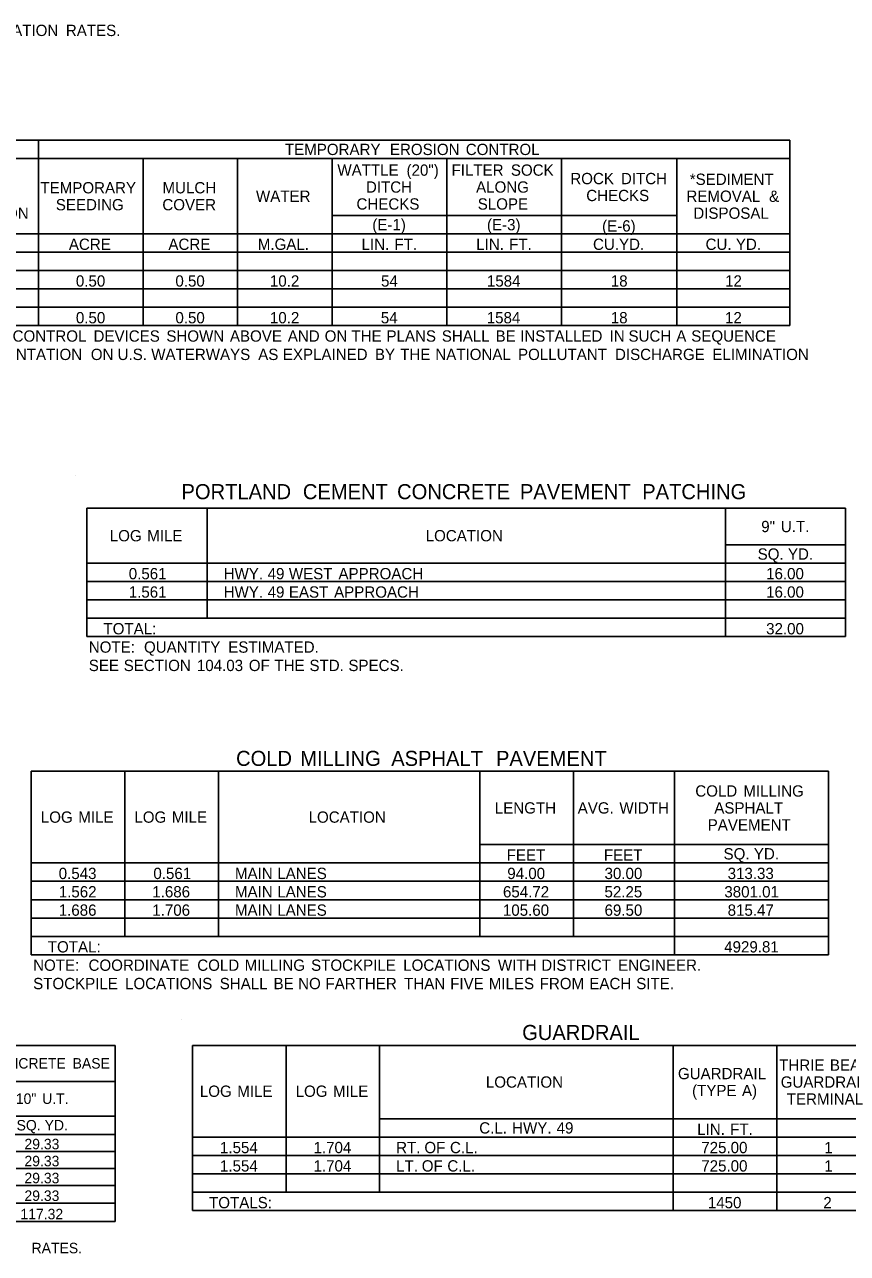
# Model space of a CAD drawing. Extents: x 107 to 7866, y 32 to 1473.
# Drawn here: x 2772 to 3209, y 41 to 694 of the extents above; entities that cross this region are included whole.
import ezdxf

# ---------------------------------------------------------------- set-up
doc = ezdxf.new("R2010")
doc.units = 0
doc.layers.add('Default', color=7, linetype='Continuous')
doc.layers.add('R_No Plot', color=7, linetype='Continuous')

msp = doc.modelspace()

# ---------------------------------------------------------------- linework, layer by layer
at = {"layer": 'Default'}
for p, q in [((2198.44, 632.71), (3178.81, 632.71)), ((2779.54, 534.24), (2779.54, 632.71)), ((2779.54, 622.96), (2779.54, 632.71)), ((3178.81, 573.24), (3178.81, 632.71)), ((2518.24, 622.96), (3178.81, 622.96)), ((2835.12, 534.24), (2835.12, 622.96)), ((2885.33, 534.24), (2885.33, 622.96)), ((2935.54, 534.24), (2935.54, 622.96)), ((2996.48, 534.24), (2996.48, 622.96)), ((3057.42, 534.24), (3057.42, 622.96)), ((3118.84, 534.24), (3118.84, 622.96)), ((2935.54, 592.74), (3118.84, 592.74)), ((2518.24, 582.99), (3178.81, 582.99)), ((2779.54, 543.99), (2779.54, 582.99)), ((2835.12, 534.24), (2835.12, 582.99)), ((2885.33, 534.24), (2885.33, 582.99)), ((2935.54, 543.99), (2935.54, 582.99)), ((2996.48, 543.99), (2996.48, 582.99)), ((3057.42, 543.99), (3057.42, 582.99)), ((3118.84, 582.99), (3178.81, 582.99)), ((3118.84, 543.99), (3118.84, 582.99)), ((2198.44, 573.24), (3178.81, 573.24)), ((3178.81, 543.99), (3178.81, 573.24)), ((2198.44, 563.49), (3178.81, 563.49)), ((2198.44, 553.74), (3178.81, 553.74)), ((2198.44, 543.99), (3178.81, 543.99)), ((2568.46, 543.99), (2779.54, 543.99)), ((2779.54, 543.99), (2835.12, 543.99)), ((2835.12, 543.99), (3178.81, 543.99)), ((3178.81, 534.24), (3178.81, 543.99)), ((2198.44, 534.24), (3178.81, 534.24)), ((2805.26, 437.25), (3208.43, 437.25)), ((2805.26, 369), (2805.26, 437.25)), ((2805.26, 369), (2805.26, 437.25)), ((2869.13, 378.75), (2869.13, 437.25)), ((3144.56, 369), (3144.56, 437.25)), ((3144.56, 417.75), (3144.56, 437.25)), ((3208.43, 369), (3208.43, 437.25)), ((3208.43, 369), (3208.43, 437.25)), ((3144.56, 417.75), (3208.43, 417.75)), ((2805.26, 408), (3208.43, 408)), ((2805.26, 408), (3208.43, 408)), ((2805.26, 398.25), (3208.43, 398.25)), ((2805.26, 388.5), (3208.43, 388.5)), ((3144.56, 378.75), (3144.56, 388.5)), ((2805.26, 378.75), (3208.43, 378.75)), ((2805.26, 378.75), (3208.43, 378.75)), ((2805.26, 369), (3208.43, 369)), ((2775.69, 297.5), (3199.33, 297.5)), ((2775.69, 200), (2775.69, 297.5)), ((2775.69, 200), (2775.69, 297.5)), ((2825.42, 209.75), (2825.42, 297.5)), ((2875.14, 209.75), (2875.14, 297.5)), ((3014.08, 209.75), (3014.08, 297.5)), ((3063.81, 209.75), (3063.81, 297.5)), ((3117.43, 200), (3117.43, 297.5)), ((3199.33, 200), (3199.33, 297.5)), ((3014.08, 258.5), (3199.33, 258.5)), ((3014.08, 209.75), (3014.08, 258.5)), ((3063.81, 248.75), (3063.81, 258.5)), ((2775.69, 248.75), (3199.33, 248.75)), ((2825.42, 209.75), (2825.42, 248.75)), ((2875.14, 209.75), (2875.14, 248.75)), ((3117.43, 209.75), (3117.43, 248.75)), ((2775.69, 239), (3199.33, 239)), ((2775.69, 229.25), (3199.33, 229.25)), ((2775.69, 219.5), (3199.33, 219.5)), ((2775.69, 209.75), (2825.42, 209.75)), ((2775.69, 209.75), (3199.33, 209.75)), ((2875.14, 209.75), (3014.08, 209.75)), ((3014.08, 209.75), (3117.43, 209.75)), ((3117.43, 209.75), (3199.33, 209.75)), ((2775.69, 200), (3199.33, 200)), ((2855.52, 165.52), (2855.52, 165.52)), ((2198.01, 151.87), (2820.2, 151.87)), ((2820.2, 58.34), (2820.2, 151.87)), ((2820.2, 58.34), (2820.2, 151.87)), ((2861.37, 151.87), (3281.6, 151.87)), ((2861.37, 64.12), (2861.37, 151.87)), ((2861.37, 64.12), (2861.37, 151.87)), ((2911.1, 73.87), (2911.1, 151.87)), ((2960.82, 73.87), (2960.82, 151.87)), ((3116.82, 64.12), (3116.82, 151.87)), ((3171.91, 64.12), (3171.91, 151.87)), ((2624.12, 132.73), (2820.2, 132.73)), ((2671.43, 114.32), (2820.2, 114.32)), ((2960.82, 112.87), (3116.82, 112.87)), ((2960.82, 112.87), (3281.6, 112.87)), ((3171.91, 64.12), (3171.91, 112.87)), ((2576.82, 104.57), (2820.2, 104.57)), ((2624.12, 104.57), (2820.2, 104.57)), ((2861.37, 103.12), (3281.6, 103.12)), ((2911.1, 73.87), (2911.1, 103.12)), ((2960.82, 73.87), (2960.82, 103.12)), ((3116.82, 64.12), (3116.82, 103.12)), ((2198.01, 95.54), (2820.2, 95.54)), ((2861.37, 93.37), (3281.6, 93.37)), ((2198.01, 86.51), (2820.2, 86.51)), ((2861.37, 83.62), (3281.6, 83.62)), ((2198.01, 77.48), (2820.2, 77.48)), ((2861.37, 73.87), (3281.6, 73.87)), ((2198.01, 68.09), (2820.2, 68.09)), ((2198.01, 68.09), (2820.2, 68.09)), ((2861.37, 64.12), (3281.6, 64.12)), ((2198.01, 58.34), (2820.2, 58.34))]:
    msp.add_line(p, q, dxfattribs=at)
at = {"layer": 'R_No Plot'}
msp.add_line((2799.41, 454.8), (2799.41, 454.8), dxfattribs=at)

# ---------------------------------------------------------------- texts
at = {"layer": 'Default'}
for s, height, p in [(' APPLICATION', 6, (2734.75, 688.06)), (' RATES.', 6, (2791.83, 688.06)), ('TEMPORARY', 6, (2910.46, 624.84)), (' EROSION', 6, (2964.04, 624.84)), (' CONTROL', 6, (3004.36, 624.84)), ('WATTLE', 6, (2938.37, 613.85)), (' (20")', 6, (2972.88, 613.85)), ('FILTER', 6, (2999.03, 613.85)), (' SOCK', 6, (3028.33, 613.85)), ('ROCK', 6, (3062.15, 609.35)), (' DITCH', 6, (3086.82, 609.35)), ('*SEDIMENT', 6, (3125.62, 608.97)), ('TEMPORARY', 6, (2780.54, 604.47)), ('MULCH', 6, (2845.41, 604.47)), ('DITCH', 6, (2953.53, 604.85)), ('ALONG', 6, (3012.07, 604.85)), ('SEEDING', 6, (2788.72, 595.47)), ('COVER', 6, (2845.34, 595.47)), ('WATER', 6, (2895.09, 599.97)), ('CHECKS', 6, (2948.51, 595.85)), ('SLOPE', 6, (3012.95, 595.85)), ('CHECKS', 6, (3070.63, 600.35)), ('REMOVAL', 6, (3123.87, 599.97)), (' &', 6, (3165.54, 599.97)), ('APPLICATION', 6, (2721.24, 590.97)), ('DISPOSAL', 6, (3127.52, 590.97)), ('(E-1)', 6, (2956.92, 584.86)), ('(E-3)', 6, (3017.86, 584.86)), ('(E-6)', 6, (3079.04, 584.19)), ('ACRE', 6, (2795.66, 574.44)), ('ACRE', 6, (2848.55, 574.44)), ('M.GAL.', 6, (2896.06, 574.44)), ('LIN.', 6, (2951.22, 574.44)), (' FT.', 6, (2966.48, 574.44)), ('LIN.', 6, (3012.16, 574.44)), (' FT.', 6, (3027.42, 574.44)), ('CU.YD.', 6, (3074.21, 574.44)), ('CU.', 6, (3134.03, 574.44)), (' YD.', 6, (3147.89, 574.44)), ('0.50', 6, (2799.38, 554.94)), ('0.50', 6, (2852.27, 554.94)), ('10.2', 6, (2902.5, 554.94)), ('54', 6, (2961.56, 554.94)), ('1584', 6, (3017.83, 554.94)), ('18', 6, (3083.66, 554.94)), ('12', 6, (3144.39, 554.94)), ('0.50', 6, (2799.38, 535.44)), ('0.50', 6, (2852.28, 535.44)), ('10.2', 6, (2902.49, 535.44)), ('54', 6, (2961.45, 535.44)), ('1584', 6, (3017.73, 535.44)), ('18', 6, (3083.66, 535.44)), ('12', 6, (3144.37, 535.44)), (' CONTROL', 6, (2763.52, 525.69)), (' DEVICES', 6, (2806.53, 525.69)), (' SHOWN', 6, (2845.23, 525.69)), (' ABOVE', 6, (2879.01, 525.69)), (' AND', 6, (2909.78, 525.69)), (' ON', 6, (2929.37, 525.69)), (' THE', 6, (2943.58, 525.69)), (' PLANS', 6, (2962.23, 525.69)), (' SHALL', 6, (2991.62, 525.69)), (' BE', 6, (3020.21, 525.69)), (' INSTALLED', 6, (3033.27, 525.69)), (' IN', 6, (3080.81, 525.69)), (' SUCH', 6, (3090.84, 525.69)), (' A', 6, (3116.24, 525.69)), (' SEQUENCE', 6, (3124.18, 525.69)), (' SEDIMENTATION', 6, (2734.51, 515.94)), (' ON', 6, (2805.09, 515.94)), (' U.S.', 6, (2819.31, 515.94)), (' WATERWAYS', 6, (2837.21, 515.94)), (' AS', 6, (2894.06, 515.94)), (' EXPLAINED', 6, (2907.14, 515.94)), (' BY', 6, (2956.08, 515.94)), (' THE', 6, (2969.53, 515.94)), (' NATIONAL', 6, (2988.18, 515.94)), (' POLLUTANT', 6, (3032.13, 515.94)), (' DISCHARGE', 6, (3083.67, 515.94)), (' ELIMINATION', 6, (3135.4, 515.94)), ('PORTLAND', 8, (2855.5, 442.02)), (' CEMENT', 8, (2917.05, 442.02)), (' CONCRETE', 8, (2967.12, 442.02)), (' PAVEMENT', 8, (3032.4, 442.02)), (' PATCHING', 8, (3097.39, 442.02)), ('LOG', 6, (2817.4, 419.62)), (' MILE', 6, (2835.06, 419.62)), ('LOCATION', 6, (2985.29, 419.62)), ('9"', 6, (3163.6, 424.5)), (' U.T.', 6, (3171.81, 424.5)), ('SQ.', 6, (3161.7, 409.87)), (' YD.', 6, (3175.57, 409.87)), ('0.561', 6, (2827.48, 399.45)), ('HWY.', 6, (2877.9, 399.45)), (' 49', 6, (2899.06, 399.45)), (' WEST', 6, (2910.34, 399.45)), (' APPROACH', 6, (2936.71, 399.45)), ('16.00', 6, (3166.21, 399.45)), ('1.561', 6, (2827.48, 389.7)), ('HWY.', 6, (2877.9, 389.7)), (' 49', 6, (2899.06, 389.7)), (' EAST', 6, (2910.34, 389.7)), (' APPROACH', 6, (2934.39, 389.7)), ('16.00', 6, (3166.21, 389.7)), ('TOTAL:', 6, (2814.04, 370.2)), ('32.00', 6, (3166.22, 370.2)), ('NOTE:', 6, (2806.24, 360.45)), ('  QUANTITY', 6, (2831.13, 360.45)), (' ESTIMATED.', 6, (2878.11, 360.45)), ('SEE', 6, (2806.24, 350.7)), (' SECTION', 6, (2822.57, 350.7)), (' 104.03', 6, (2861.48, 350.7)), (' OF', 6, (2889.06, 350.7)), (' THE', 6, (2902.64, 350.7)), (' STD.', 6, (2921.29, 350.7)), (' SPECS.', 6, (2941.99, 350.7)), ('COLD', 8, (2884.52, 300.32)), (' MILLING', 8, (2915.63, 300.32)), (' ASPHALT', 8, (2964, 300.32)), (' PAVEMENT', 8, (3019.67, 300.32)), ('COLD', 6, (3128.57, 284)), (' MILLING', 6, (3151.91, 284)), ('LENGTH', 6, (3022.03, 275)), ('AVG.', 6, (3066.08, 275)), (' WIDTH', 6, (3086, 275)), ('ASPHALT', 6, (3138.67, 275)), ('LOG', 6, (2780.76, 270.12)), (' MILE', 6, (2798.42, 270.12)), ('LOG', 6, (2830.48, 270.12)), (' MILE', 6, (2848.14, 270.12)), ('LOCATION', 6, (2923.06, 270.12)), ('PAVEMENT', 6, (3135.17, 266)), ('FEET', 6, (3028.32, 249.95)), ('FEET', 6, (3079.99, 249.95)), ('SQ.', 6, (3143.58, 250.62)), (' YD.', 6, (3157.45, 250.62)), ('0.543', 6, (2790.26, 240.2)), ('0.561', 6, (2840.57, 240.2)), ('MAIN', 6, (2883.92, 240.2)), (' LANES', 6, (2904.19, 240.2)), ('94.00', 6, (3028.66, 240.2)), ('30.00', 6, (3080.34, 240.2)), ('313.33', 6, (3145.76, 240.2)), ('1.562', 6, (2790.29, 230.45)), ('1.686', 6, (2839.99, 230.45)), ('MAIN', 6, (2883.92, 230.45)), (' LANES', 6, (2904.19, 230.45)), ('654.72', 6, (3026.35, 230.45)), ('52.25', 6, (3080.3, 230.45)), ('3801.01', 6, (3144.01, 230.45)), ('1.686', 6, (2790.26, 220.7)), ('1.706', 6, (2839.99, 220.7)), ('MAIN', 6, (2883.92, 220.7)), (' LANES', 6, (2904.19, 220.7)), ('105.60', 6, (3026.33, 220.7)), ('69.50', 6, (3080.34, 220.7)), ('815.47', 6, (3145.76, 220.7)), ('TOTAL:', 6, (2784.47, 201.2)), ('4929.81', 6, (3143.92, 201.2)), ('NOTE:', 6, (2776.67, 191.45)), (' COORDINATE', 6, (2803.88, 191.45)), (' COLD', 6, (2861.66, 191.45)), (' MILLING', 6, (2886.83, 191.45)), (' STOCKPILE', 6, (2922.17, 191.45)), (' LOCATIONS', 6, (2971.11, 191.45)), (' WITH', 6, (3021.44, 191.45)), (' DISTRICT', 6, (3044.51, 191.45)), (' ENGINEER.', 6, (3085.33, 191.45)), ('STOCKPILE', 6, (2776.67, 181.7)), (' LOCATIONS', 6, (2823.28, 181.7)), (' SHALL', 6, (2873.61, 181.7)), (' BE', 6, (2902.21, 181.7)), (' NO', 6, (2915.27, 181.7)), (' FARTHER', 6, (2929.8, 181.7)), (' THAN', 6, (2971.61, 181.7)), (' FIVE', 6, (2996.08, 181.7)), (' MILES', 6, (3016.59, 181.7)), (' FROM', 6, (3043.64, 181.7)), (' EACH', 6, (3070.01, 181.7)), (' SITE.', 6, (3094.96, 181.7)), ('GUARDRAIL', 8, (3036.57, 154.7)), (' CONCRETE', 5.556, (2750.24, 139.53)), (' BASE', 5.556, (2795.57, 139.53)), ('THRIE', 6, (3173.15, 138.37)), (' BEAM', 6, (3197.88, 138.37)), ('GUARDRAIL', 6, (3119.34, 133.87)), ('LOG', 6, (2865.27, 124.5)), ('LOG', 6, (2916.16, 124.5)), ('LOCATION', 6, (3017.27, 129.37)), ('(TYPE', 6, (3126.86, 124.87)), (' A)', 6, (3151.14, 124.87)), ('GUARDRAI', 6, (3173.97, 129.37)), ('10"', 5.556, (2767.46, 120.75)), (' U.T.', 5.556, (2779.39, 120.75)), (' MILE', 6, (2882.93, 124.5)), (' MILE', 6, (2933.82, 124.5)), ('TERMINAL', 6, (3177.19, 120.37)), ('SQ.', 5.556, (2767.86, 106.66)), (' YD.', 5.556, (2780.7, 106.66)), ('C.L.', 6, (3013.75, 105)), (' HWY.', 6, (3029, 105)), (' 49', 6, (3052.64, 105)), ('LIN.', 6, (3129.58, 104.32)), (' FT.', 6, (3144.83, 104.32)), ('29.33', 5.556, (2772.03, 96.65)), ('1.554', 6, (2875.96, 94.57)), ('1.704', 6, (2925.68, 94.57)), ('RT.', 6, (2969.6, 94.57)), (' OF', 6, (2982.37, 94.57)), (' C.L.', 6, (2995.96, 94.57)), ('725.00', 6, (3131.75, 94.57)), ('1', 6, (3197.16, 94.57)), ('29.33', 5.556, (2772.03, 87.62)), ('1.554', 6, (2875.96, 84.82)), ('1.704', 6, (2925.68, 84.82)), ('LT.', 6, (2969.6, 84.82)), (' OF', 6, (2980.98, 84.82)), (' C.L.', 6, (2994.56, 84.82)), ('725.00', 6, (3131.75, 84.82)), ('1', 6, (3197.16, 84.82)), ('29.33', 5.556, (2772.03, 78.59)), ('29.33', 5.556, (2772.03, 69.21)), ('TOTALS:', 6, (2870.15, 65.32)), ('1450', 6, (3135.25, 65.32)), ('2', 6, (3196.6, 65.32)), ('117.32', 5.556, (2769.9, 59.46)), (' RATES.', 5.556, (2773.76, 41.4))]:
    msp.add_text(s, height=height, dxfattribs=at).set_placement(p)

doc.saveas('drawing.dxf')
